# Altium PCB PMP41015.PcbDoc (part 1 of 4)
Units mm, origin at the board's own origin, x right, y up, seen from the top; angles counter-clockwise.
Board outline 173 x 85 mm, 2 copper layers (Top Layer, Bottom Layer), stack 1.575 mm thick; 89 components, 48 nets, 216 pads, 3458 vias.
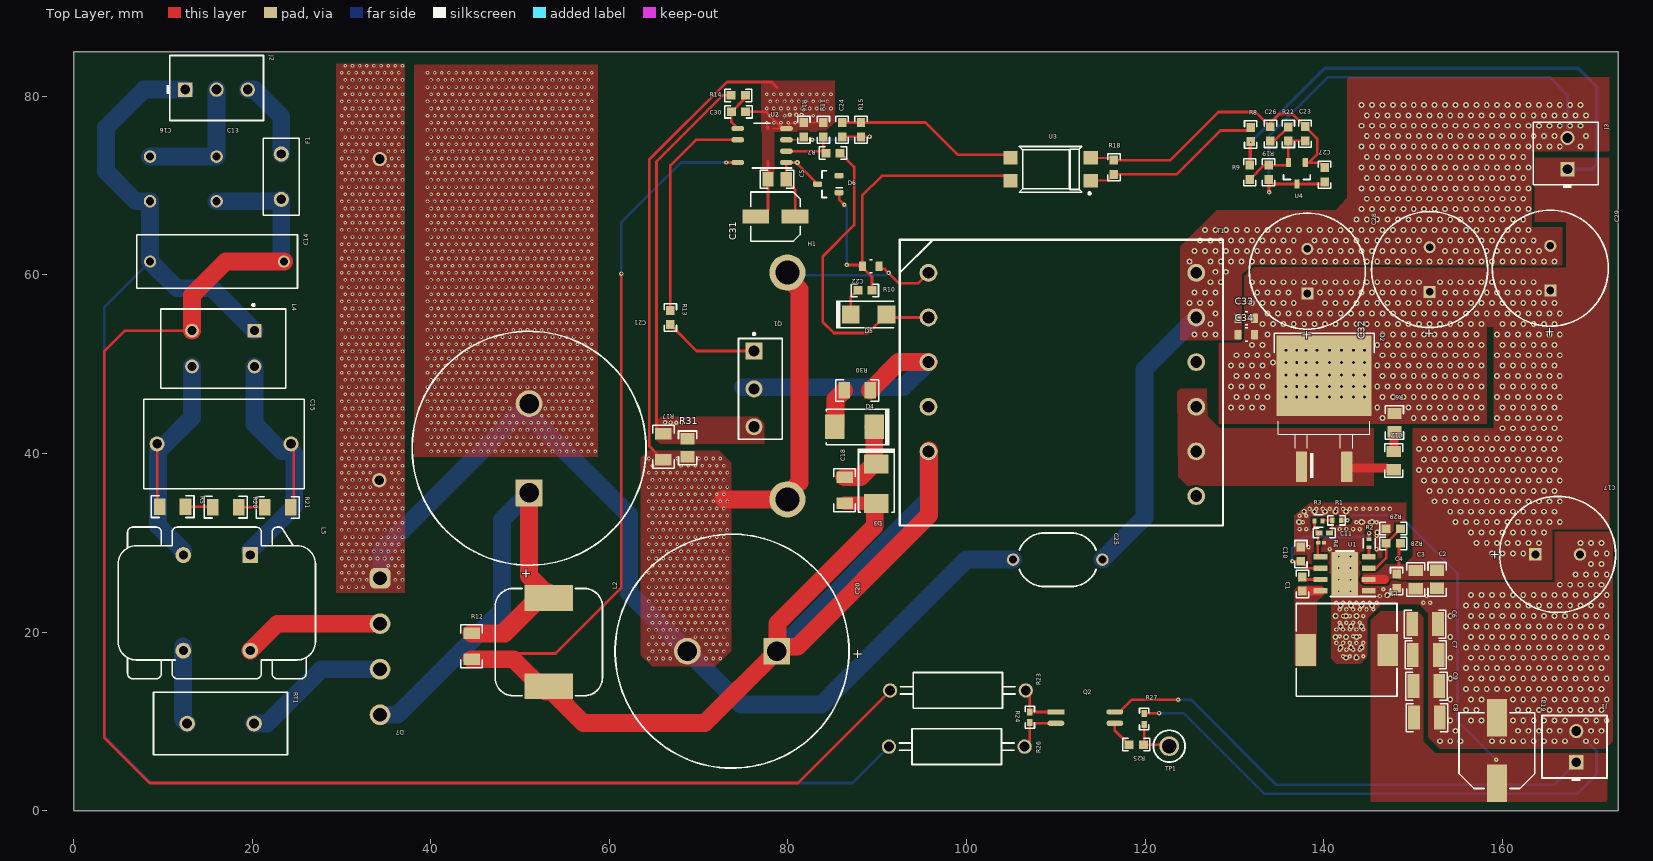
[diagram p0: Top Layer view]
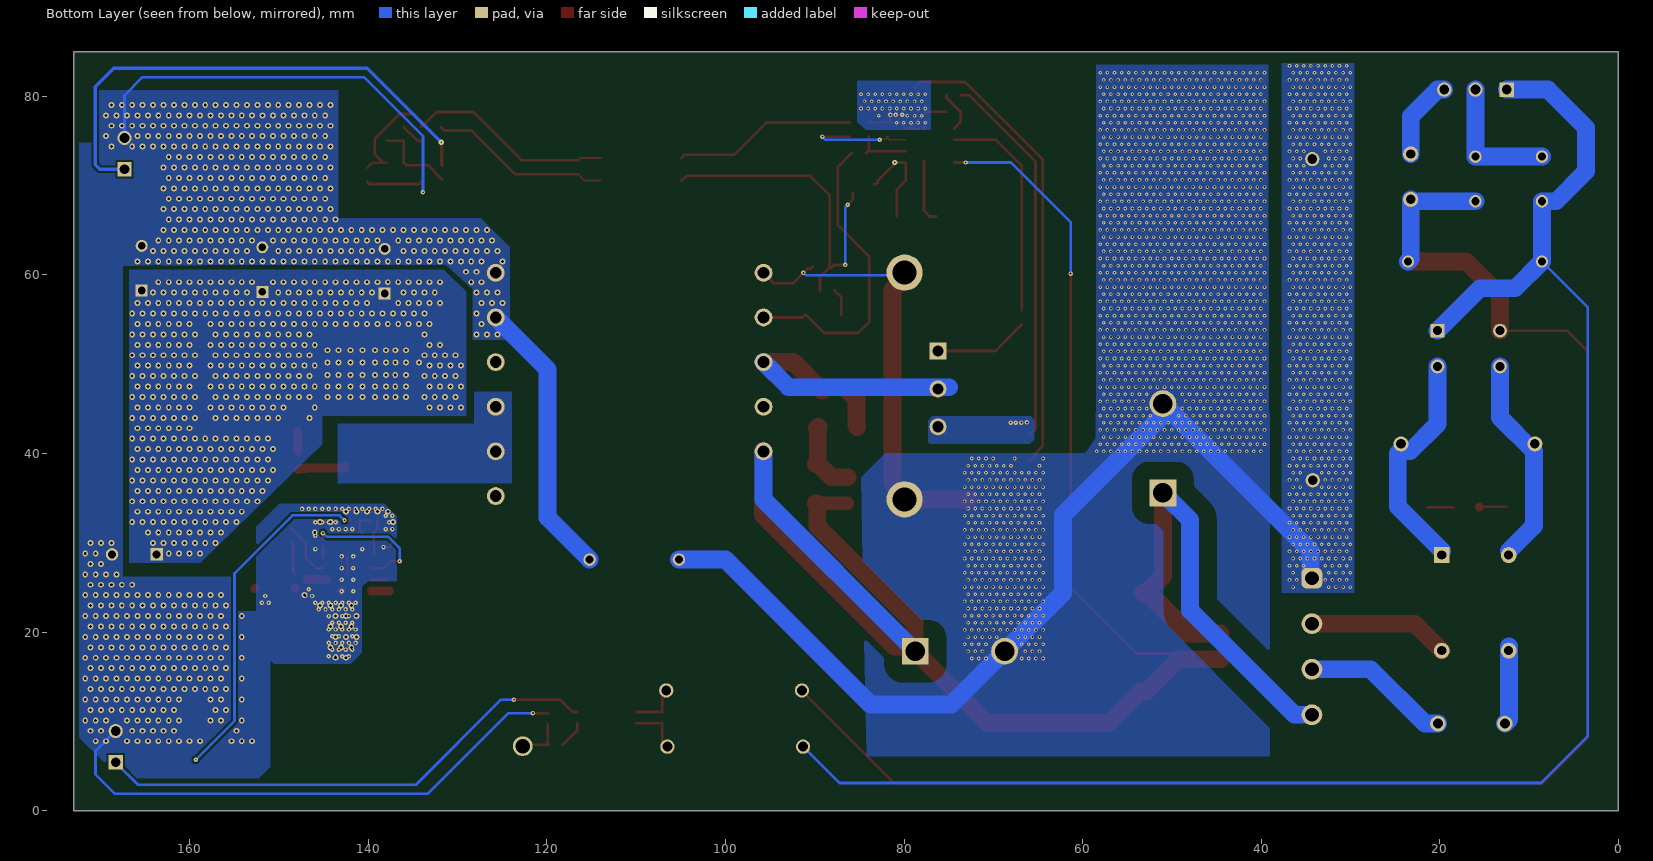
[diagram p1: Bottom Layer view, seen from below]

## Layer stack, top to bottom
Top Solder: solder mask 0.0102, Solder Resist, Dk 3.5
Top Layer: signal copper 0.0356
Dielectric1: core 1.5037, FR-4 High Tg, Dk 4.8
Bottom Layer: signal copper 0.0356
Bottom Solder: solder mask 0.0102, Solder Resist, Dk 3.5

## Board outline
0,0 173,0 173,85 0,85

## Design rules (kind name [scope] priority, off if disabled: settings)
AcuteAngle [All] p1: minimum=4.50000000000000E+0001 checktracksonly=FALSE
AssemblyTestPointUsage [All] p1: valid=2
BoardOutlineClearance BoardOutlineClearance_MountingHoles [OnCopper and InComponentClass('Mounting Holes')] p1: gap=1 ignorepadtopadclearanceinfootprint=FALSE
BoardOutlineClearance BoardOutlineClearance_Poly [OnCopper and IsPoly] p2: gap=0.635 ignorepadtopadclearanceinfootprint=FALSE
BoardOutlineClearance [OnCopper and Not InComponentClass('Logo') and not InComponentClass('FiducialMark') and not InRegion(1000,500,4000,800) and not InPoly] p3: gap=1.016 ignorepadtopadclearanceinfootprint=FALSE
Clearance Clearance_2 [InNet('PGND') vs InNet('NetC21_1')] p1: gap=2 ignorepadtopadclearanceinfootprint=TRUE
Clearance Clearance_1 [InNet('PGND') vs InNet('VDCBUS')] p2: gap=2 ignorepadtopadclearanceinfootprint=TRUE
Clearance Clearance_Keepouts [((IsTrack Or IsArc) And Not InPoly) And IsFree and IsKeepOut vs ((IsTrack Or IsArc) And Not InPoly) And IsFree and IsKeepOut] p3: gap=0 ignorepadtopadclearanceinfootprint=FALSE
Clearance Clearance_Poly [InPolygon] p4: gap=0.254 ignorepadtopadclearanceinfootprint=TRUE
Clearance Clearance_FiducialMark [IsKeepOut and InComponentClass('FiducialMark') vs IsPad and InComponentClass('FiducialMark')] p5: gap=0 ignorepadtopadclearanceinfootprint=FALSE
Clearance [All] p6: gap=0.2 ignorepadtopadclearanceinfootprint=TRUE
ComponentClearance ComponentClearance_MountingHoles_FiducialMarks [InComponentClass('Mounting Holes') vs InComponentClass('FiducialMark')] p1: gap=1.27 collisioncheckmode=3 verticalgap=0.254 showdistances=FALSE
ComponentClearance ComponentClearance_Shunt [InComponentClass('Header') vs InComponentClass('Shunt')] p2: gap=0 collisioncheckmode=3 verticalgap=0 showdistances=FALSE
ComponentClearance ComponentClearance_Logo [InComponentClass('Logo')] p3: gap=0.762 collisioncheckmode=3 verticalgap=0.254 showdistances=FALSE
ComponentClearance ComponentClearance_ScrewToNut [(HasFootprint('NY PMS 440 0025 PH')) vs (HasFootprint('Keystone_1902C'))] p4: gap=0.127 collisioncheckmode=3 verticalgap=0.254 showdistances=FALSE
ComponentClearance ComponentClearance_MountingHoles [InComponentClass('Mounting Holes')] p5: gap=2.54 collisioncheckmode=3 verticalgap=2540 showdistances=FALSE
ComponentClearance ComponentClearance_SmallPassives [HasFootprint('0201*') or HasFootprint('0402*') or HasFootprint('0508') or HasFootprint('0603*') or HasFootprint('0612') or HasFootprint('0805*') or HasFootprint('0815*') or HasFootprint('0830*') or HasFootprint('1206*') or HasFootprint('1210*') or HasFootprint('1808*') or HasFootprint('1812*') or HasFootprint('1825*') or HasFootprint('2010*') or HasFootprint('2220*') or HasFootprint('2225*') or HasFootprint('2512*') or HasFootprint('2728*') or HasFootprint('3518*') vs HasFootprint('0201*') or HasFootprint('0402*') or HasFootprint('0508') or HasFootprint('0603*') or HasFootprint('0612') or HasFootprint('0805*') or HasFootprint('0815*') or HasFootprint('0830*') or HasFootprint('1206*') or HasFootprint('1210*') or HasFootprint('1808*') or HasFootprint('1812*') or HasFootprint('1825*') or HasFootprint('2010*') or HasFootprint('2220*') or HasFootprint('2225*') or HasFootprint('2512*') or HasFootprint('2728*') or HasFootprint('3518*')] p6: gap=0.38 collisioncheckmode=3 verticalgap=0.254 showdistances=FALSE
ComponentClearance ComponentClearance_THtoSMT [IsThruComponent vs IsSMTComponent] p7: gap=0.762 collisioncheckmode=3 verticalgap=0.762 showdistances=FALSE
ComponentClearance ComponentClearance_THtoTH [IsThruComponent vs IsThruComponent] p8: gap=0.508 collisioncheckmode=3 verticalgap=0.762 showdistances=FALSE
ComponentClearance [All] p9: gap=0.508 collisioncheckmode=3 verticalgap=0.254 showdistances=FALSE
DiffPairsRouting [All] p1: maxlimit=2.54 minlimit=0.254 mostfreqgap=0.254 toplayer_minwidth=0.381 toplayer_maxwidth=0.381 toplayer_prefwidth=0.381 bottomlayer_minwidth=0.381 bottomlayer_maxwidth=0.381 bottomlayer_prefwidth=0.381 maxuncoupledlength=25.4
FabricationTestPointUsage TestPointUsage [All] p1: valid=2 allowmultiple=FALSE
FabricationTestpoint Testpoint [All] p1: side=3 testpointundercomponent=TRUE minsize=1.016 maxsize=2.54 preferedsize=1.524 minholesize=0 maxholesize=1.016 preferedholesize=0.813 testpointgrid=0.025 allowsidetop=TRUE allowsidebottom=TRUE usegrid=TRUE gridtolerance=0
FanoutControl Fanout_LCC [IsLCC] p1: bgadir=Out bgaviamode=Centered fanoutstyle=Auto fanoutdirection=Alternating viagrid=0.025 // Fanout_LCC (Default Rule)
FanoutControl Fanout_BGA [IsBGA] p2: bgadir=Out bgaviamode=Centered fanoutstyle=Auto fanoutdirection=Alternating viagrid=0.025 // Fanout_BGA (Default Rule)
FanoutControl Fanout_Default [All] p4: bgadir=Out bgaviamode=Centered fanoutstyle=Auto fanoutdirection=Alternating viagrid=0.025 // Fanout_Default (Default Rule)
FanoutControl Fanout_Small [(CompPinCount < 5)] p5: bgadir=Out bgaviamode=Centered fanoutstyle=Auto fanoutdirection=OutThenIn viagrid=0.025 // Fanout_Small (Default Rule)
HoleSize [All] p1: absolutevalues=TRUE maxlimit=6.375 minlimit=0.2 maxpercent=80.000 minpercent=20.000
MinimumAnnularRing MinimumAnnularRing_ThermalPadVias [IsVia and InAnyComponent] p1: minimumring=0.15
MinimumAnnularRing [All] p2: minimumring=0.2
MinimumSolderMaskSliver MinimumSolderMaskSliver_Logo [InComponentClass('Logo') vs InComponentClass('Logo')] p1: minsoldermaskwidth=0.018
MinimumSolderMaskSliver [All] p2: minsoldermaskwidth=0.1
PlaneConnect [All] p1: planeconnectstyle=Direct reliefexpansion=0.254 reliefentries=4 reliefconductorwidth=0.254 reliefairgap=0.254
PolygonConnect [All] p1: connectstyle=Direct reliefconductorwidth=0.254 reliefentries=4 polygonreliefangle="90 Angle" airgapwidth=0.254
RoutingVias ThermalPadVias [IsVia and InAnyComponent] p1: holewidth=0.2 width=0.5 viastyle="Through Hole" minholewidth=0.1 minwidth=0.1 maxholewidth=0.33 maxwidth=0.6
RoutingVias [All] p2: holewidth=0.406 width=0.864 viastyle="Through Hole" minholewidth=0.1 minwidth=0.1 maxholewidth=1.016 maxwidth=1.651
SilkToBoardRegionClearance [Not ((IsComment or IsDesignator) And (Hide <> 'False')) and not InRegion(1000,500,4000,800)] p1:
SilkToSilkClearance SilkToSilkClearance_Pb-FreeLogo [(HasFootprint('Pb-Free_Overlay_Medium') OR HasFootprint('Pb-Free_Overlay_Small')) vs (HasFootprint('Pb-Free_Overlay_Medium') OR HasFootprint('Pb-Free_Overlay_Small'))] p1: silktosilkclearance=0
SilkToSilkClearance [All] p2: silktosilkclearance=0.1
SilkToSolderMaskClearance SilkToComponentPadClearance [(IsPad or IsFill or IsRegion) and InAnycomponent] p1: minsilkscreentomaskgap=0.127 clearancetoexposedcopper=TRUE
SilkToSolderMaskClearance "Silk to Solder Mask Opening" [All] p2: minsilkscreentomaskgap=0.1 clearancetoexposedcopper=FALSE
SolderMaskExpansion [All] p1: expansion=0.05 istentingtop=FALSE
UnRoutedNet [All] p1: checkbadconnections=TRUE
Width [All] p1: maxlimit=2.54 minlimit=0.3 preferedwidth=2 checkconnectedcopper=TRUE
14 further rules are at their usual default settings.

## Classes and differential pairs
net class "HV BUS": NetQ1_2 VDCBUS
component class PMP41015_DCDC: C1 C2 C3 C4 C6 C7 C8 C9 C10 C11 C17 C19 J1 L1 R1 R2 R3 R4 R28 R29 U1
component class PMP41015_ACDC: C5 C12 C13 C14 C15 C16 C18 C20 C21 C22 C23 C24 C25 C26 C27 C28 C29 C30 C31 C32 C33 C34 D2 D3 D4 D5 D6 D7 F1 H1 J2 J3 L2 L4 L5 Q1 Q2 R5 R6 R7 R8 R9 R10 R11 R12 R13 R14 R15 R16 R17 R18 R19 R20 R21 R22 R23 R24 R25 R26 R27 R30 R31 RT1 T1 TP1 U2 U3 U4

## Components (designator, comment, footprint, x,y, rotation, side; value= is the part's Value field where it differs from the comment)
C1 "0.1uF" 0603 137.623,25.377 r270 top
C2 "4.7uF" 0805_HV 152.704,25.908 r270 top
C3 "4.7uF" 0805_HV 150.316,25.883 r270 top
C4 "0.22uF" 0603 148.178,25.705 r270 top
C5 "C2012X7R1H225K125AC" 0805_HV 78.774,70.726 r180 top value=2.2uF
C6 "" 1210 151.359,20.879 r0 top value=22uF
C7 "CMP-0009169-2" 1210 151.435,17.45 r0 top value=22uF
C8 "CMP-0009169-2" 1210 151.565,10.414 r0 top value=22uF
C9 "CMP-0009169-2" 1210 151.511,13.945 r0 top value=22uF
C10 "CMP-0006833-4" 0603 137.446,28.73 r90 top value=1uF
C11 "CMP-0006207-2" 0402 140.073,31.09 r180 top value=10pF
C12 "CMP-0007712-2" 0805_HV 147.852,39.208 r90 top value=1000pF
C13 "VY2222M35Y5UG6TV5" VY2_900x500_5 16,70.75 r90 top value=2200pF
C14 "ECQ-U2A104ML" CAPRR1500W60L1750T550H1250 16.05,61.5 r180 top value=0.1uF
C15 "ECQ-U2A334ML" CAPRR1500W80L1750T950H1750 16.84,41.072 r0 top value=0.33uF
C16 "VY2222M35Y5UG6TV5" VY2_900x500_5 8.55,70.75 r270 top value=2200pF
C17 "CMP-0010315-2" B41896_1250x2500 166.206,28.695 r0 top value=680uF
C18 "CMP-0008891-2" 1206 86.335,35.89 r90 top value=1000pF
C19 "CMP-0010819-1" CAPSMT_62_HA0 159.41,6.731 r90 top value=680uF
C20 "CMP-0010099-2" Nichicon_2500x3000_Snap 73.736,17.856 r180 top value=120uF
C21 "CMP-0010099-2" Nichicon_2500x3000_Snap 51.003,40.585 r90 top value=120uF
C22 "CGA4J1X7R1H475K125AC" FP-CGA4J1X7R1H475K125AC_0805-MFG 89.29,60.96 r180 top value=4.7µF
C23 "06035C561KAT2A" 0603 137.922,75.815 r90 top value=560pF
C24 "CMP-0007015-5" 0603 86.064,76.27 r90 top value=0.047uF
C25 "CD45-E2GA222M-NKA" CD45_900x600x1300 110.211,28.118 r0 top value=2200pF
C26 "C0603C332F5GACTU" 0603 134.036,75.791 r90 top value=3300pF
C27 "CMP-0006752-5" 0603 140.106,71.209 r270 top value=0.1uF
C28 "ELXZ350ELL102MK25S" Chemi-Con_1250x2000 138.168,60.42 r90 top value=1000uF
C29 "ELXZ350ELL102MK25S" Chemi-Con_1250x2000 165.384,60.754 r90 top value=1000uF
C30 "CMP-0006939-4" 0603 74.464,78.27 r0 top value=47pF
C31 "CMP-0011424-2" SM_RADIAL_5MM 78.603,66.541 r180 top value=4.7uF
C32 "ELXZ350ELL102MK25S" Chemi-Con_1250x2000 151.869,60.599 r90 top value=1000uF
C33 "C2012X7R1H475K125AC" FP-C2012X7R1H475K125AC_0805-MFG 131.343,55.143 r0 top
C34 "C2012X7R1H475K125AC" FP-C2012X7R1H475K125AC_0805-MFG 131.343,53.315 r0 top
D2 "MBRB20200CTT4G" DDPAK 140.046,44.743 r90 top value=200V
D3 "CMP-0005579-3" SMB 89.891,36.601 r270 top value=170V
D4 "CMP-0076889-2" SMB 87.452,42.977 r180 top value=1000V
D5 "US1J-13-F" SMA 89.027,55.575 r0 top value=600V
D6 "CMP-0028436-2" SOT-23 84.518,70.162 r180 top value=40V
D7 "KBU8J-E4/51" KBU 32.795,18.383 r270 top value=600V
F1 "39215000000" FUSE_392 23.25,71 r90 top
H1 "V6560W" HSINK_V6560W 79.93,47.562 r270 top
J1 "0393570002" MOLEX_39357-0002 168.3,7.163 r90 top
J2 "0393570003" MOLEX_39357-0003 16,80.75 r0 top
J3 "0393570002" MOLEX_39357-0002 167.307,73.594 r90 top
L1 "=Value" WE-HCC_1090 142.573,18.009 r0 top
L2 "7447709821" WE-PD_1210 53.211,18.876 r270 top value=820uH
L4 "750343092" FP-750343092_PTH_14MM0_8MM89-0 16.75,51.75 r270 top
L5 "744823220" WE-CMB_M 16.027,23.266 r270 top value=20mH
Q1 "TK10A80W" FP-IPAW60R360P7SXKSA1_PG-TO220-3-MFG 76.898,47.236 r0 top
Q2 "TLP292(GR-TPL,E" FP-TLP292(GR-TPL,E_SO4-IPC_A 113.303,10.418 r0 top
R1 "CMP-0026765-1" CPF0402 141.453,32.512 r0 top value=10.0
R2 "CRCW0402100KFKEDC" FP-CRCW0402100KFKEDC_0402-MFG 145.085,29.947 r90 top value=100k
R3 "CRCW0402100KFKEDC" FP-CRCW0402100KFKEDC_0402-MFG 139.421,32.436 r0 top value=100k
R4 "RC0201FR-0723K7L" 0201 139.724,29.987 r180 top value=23.7k
R5 "CMP-0017156-3" 1206 11.074,34.036 r180 top value=750k
R6 "CMP-0020804-2" 0805_HV 147.926,43.456 r90 top value=10
R7 "CMP-0022628-4" 0603 85.039,73.64 r0 top value=86.6k
R8 "CMP-0022883-5" 0603 131.826,75.726 r270 top value=1.50k
R9 "CMP-0024170-3" 0603 131.724,71.488 r90 top value=383k
R10 "CMP-0025703-4" 0603 88.621,58.268 r180 top value=10
R11 "CMP-0022220-4" 0603 83.964,76.27 r270 top value=22.1k
R12 "CMP-0018656-3" 1206 44.571,18.397 r270 top value=330k
R13 "ERJ-3RQF2R2V" 0603 66.827,55.234 r270 top value=2.20
R14 "CMP-0022109-5" 0603 74.435,80.11 r180 top value=1.00k
R15 "CMP-0022735-5" 0603 88.181,76.27 r270 top value=100k
R16 "CMP-0022925-5" 0603 81.775,76.249 r270 top value=22.0k
R17 "CMP-0017788-3" 1206 66.048,40.767 r90 top value=0.33
R18 "CMP-0023354-3" 0603 116.51,72.06 r270 top value=4.99k
R19 "CMP-0023118-5" 0603 133.833,71.488 r90 top value=44.2k
R20 "CMP-0017156-3" 1206 17.018,33.985 r180 top value=750k
R21 "CMP-0017156-3" 1206 22.86,33.96 r180 top value=750k
R22 "CMP-0021998-4" 0603 136.043,75.79 r270 top value=10.0k
R23 "CMP-0014401-2" PR02 99.035,13.462 r0 top value=47k
R24 "CMP-0026891-5" 0402 107.088,10.453 r90 top value=2.4k
R25 "CMP-0025697-4" 0603 118.999,7.391 r0 top value=0
R26 "CMP-0014401-2" PR02 98.908,7.163 r0 top value=47k
R27 "CMP-0025983-3" 0402 119.893,10.262 r270 top value=120k
R28 "CMP-0021990-4" 0603 147.797,29.919 r0 top value=100k
R29 "CMP-0022746-5" 0603 147.803,31.595 r0 top value=10.0k
R30 "CMP-0018687-3" 1206 87.757,47.066 r180 top value=47
R31 "CMP-0020847-3" 0805_HV 68.759,40.634 r90 top value=10.0
RT1 "B57237S0479M000" S237 16.452,9.75 r0 top value=4.7
T1 "750345036" "EE28 FROM CUSTOMER" 95.733,60.234 r0 top value=300uH
TP1 "5011" Keystone5011 122.707,7.216 r180 top
U1 "LMR33620ADDAR" DDA0008J 142.348,26.518 r180 top
U2 "UCC28740DR" D0007A_N 77.1,74.495 r180 top
U3 "LTV-817S" DIP254P762X350-4 109.423,71.831 r180 top
U4 "TL431LIBQDBZR" DBZ0003A_N 137.008,71.378 r270 top

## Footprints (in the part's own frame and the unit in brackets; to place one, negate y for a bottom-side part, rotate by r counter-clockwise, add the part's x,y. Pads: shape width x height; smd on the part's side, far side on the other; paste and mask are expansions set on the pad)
0201 [mm] "Data from Kemet datasheet CC101_COM dated 7/28/11"
  rect 0.46x0.42 smd mask+0.048: 1(-0.33,0) 2(0.33,0)
  body extent -0.31,-0.16 0.31,0.16, height 0.26
0402 [mm] "0402 from SM-752 data"
  rect 0.8x0.6 smd: 1(-0.6,0) 2(0.6,0)
  silkscreen extent -1.22,-0.52 1.22,0.52, body extent -0.55,-0.3 0.55,0.3, height 0.6
0603 [mm] "0603 from SM-752 data"
  rect 1x0.95 smd: 1(-0.8,0) 2(0.8,0)
  silkscreen extent -1.52,-0.69 1.52,0.69, body extent -0.87,-0.47 0.87,0.47, height 1
0805_HV [mil] "0805 with 30mil clearance between pads"
  rect 50x63 smd: 1(-40,0) 2(40,0)
  silkscreen extent -74,-40 74,40, body extent -43,-29 43,29, height 57
1206 [mm] "1206 from SM-752 data"
  rect 1.3x1.85 smd: 1(-1.45,0) 2(1.45,0)
  silkscreen extent -2.4,-1.21 2.4,1.21, body extent -1.7,-0.9 1.7,0.9, height 1.35
1210 [mm] "1210 from SM-752 data"
  rect 1.3x2.7 smd: 1(-1.45,0) 2(1.45,0)
  silkscreen extent -2.32,-1.57 2.32,1.57, body extent -1.7,-1.35 1.7,1.35, height 1.35
B41896_1250x2500 [mm] "TH, 2-Leads, Dia 12.5mm, Pin Spacing 5mm"
  rect 1.4x1.4 hole 0.9: 1(-2.5,0)
  round 1.4 hole 0.9: 2(2.5,0)
  silkscreen extent -6.5,-6.5 6.5,6.5, body extent -6.5,-6.5 6.51,6.5, height 27.01
CAPRR1500W60L1750T550H1250 [mm] "PANASONIC"
  round 1.35 hole 0.85: 1(-7.5,0) 2(7.5,0)
  silkscreen extent -9,-3 9,3, body extent -9.05,-3.05 9.05,3.05, height 13
CAPRR1500W80L1750T950H1750 [mm] "PANASONIC"
  round 1.7 hole 1.069: 1(-7.5,0) 2(7.5,0)
  silkscreen extent -9,-5 9,5, body extent -9,-5 9,5, height 18
CAPSMT_62_HA0 [mm] "8 x 10mm:  Chemi-Con HA0"
  rect 4.2x2.2 smd: 1(-3.65,0) 2(3.65,0)
  silkscreen extent -4.25,-4.25 4.25,4.25, body extent -4.25,-4.25 4.25,4.25, height 10.5
CD45_900x600x1300 [mm] "TH, 2-Leads, Dia 9mm, Pin Spacing 10 mm"
  round 1.4 hole 0.9: 1(-5,0) 2(5,0)
  silkscreen extent -4.29,-3.02 4.3,2.98, body extent -5.39,-3.01 5.39,3.01, height 13
Chemi-Con_1250x2000 [mm] "TH, 2-Leads, Dia 12.5mm, Lead Sapcing 5mm"
  rect 1.35x1.35 hole 0.85: 1(-2.5,0)
  round 1.35 hole 0.85: 2(2.5,0)
  silkscreen extent -6.5,-6.5 6.5,6.5, body extent -6.5,-6.5 6.51,6.5, height 21.5
CPF0402 [mm] "TE Connectivity"
  rect 0.5x0.6 smd: 1(-0.5,0) 2(0.5,0)
  silkscreen extent -0.97,-0.53 0.97,0.53, body extent -0.55,-0.27 0.55,0.27, height 0.35
D0007A_N [mm] "SOIC, 7-Leads, Body 4.9x3.9mm, Pitch 1.27mm, IPC Medium Density"
  oval 1.45x0.6 smd: 1(-2.725,1.905) 2(-2.725,0.635) 3(-2.725,-0.635) 4(-2.725,-1.905) 5(2.725,-1.905) 6(2.725,-0.635) 8(2.725,1.905)
  silkscreen extent -3.32,-2.5 1.1,2.52, body extent -3.01,-2.45 3.01,2.45, height 1.75
DBZ0003A_N [mm] "SOT23, 3-Leads, Body 2.9x1.3mm, Pitch 0.95mm, Lead Span 2.4mm, IPC Medium Density"
  rrect17% 1x0.6 smd: 1(-1.2,0.95) 2(-1.2,-0.95) 3(1.2,0)
  silkscreen extent 0.2,-1.5 0.7,1.5, body extent -1.26,-1.46 1.26,1.46, height 0.98
DDA0008J [mm] "SOIC, 8-Leads, Body 4.9x3.9mm, Pitch 1.27mm, Exposed Pad"
  rrect14% 1.55x0.6 smd: 1(-2.7,1.905) 2(-2.7,0.635) 3(-2.7,-0.635) 4(-2.7,-1.905) 5(2.7,-1.905) 6(2.7,-0.635) 7(2.7,0.635) 8(2.7,1.905)
  rrect4% 2.95x4.9 smd paste-1.5 mask-1.5: 9(0,0)
  silkscreen extent -3.47,-2.55 1.58,2.55, body extent -3.01,-2.45 3.01,2.45, height 1.57
DDPAK [mil] "D2-PAK, 3-Pads, Body 9.7x10.4mm (max), TO-263AB, using Vishay Silionix recommended pad sizes"
  rrect8% 135x49.49 smd: 1(-246.06,100) 3(-246.06,-100)
  rrect1% 355x420 smd paste-181.1: 4(155.51,0)
  silkscreen extent -295,-220 344,220, body extent -295,-202 324,202, height 180
DIP254P762X350-4 [mm] "LITE-ON"
  rect 1.6x1.5 smd: 1(-4.5,1.27) 2(-4.5,-1.27) 3(4.5,-1.27) 4(4.5,1.27)
  silkscreen extent -4.47,-2.55 3.5,2.82, body extent -5.23,-2.55 5.23,2.55, height 4.62
"EE28 FROM CUSTOMER" [mm]
  round 2 hole 1.32: 1(0,0) 2(0,-5) 3(0,-10) 4(0,-15) 5(0,-20) 7(30,-25) 8(30,-20) 9(30,-15) 10(30,-10) 11(30,-5) 12(30,0)
  round 0 all layers, no hole: 6(0,-25)
  silkscreen extent -3.2,-28.3 33,3.7
FP-750343092_PTH_14MM0_8MM89-0 [mm]
  rrect6% 1.55x1.55 hole 1 paste-1000 mask+0: 1(-2,3.5)
  round 1.55 hole 1 paste-1000 mask+0: 2(2,3.5) 3(2,-3.5) 4(-2,-3.5)
  silkscreen extent -5,-7 4.45,7, body extent -4.61,-7 4.58,7, height 18.5
FP-C2012X7R1H475K125AC_0805-MFG [mm]
  rrect13% 0.8x1.05 smd paste+0 mask+0: 1(-0.925,0) 2(0.925,0)
  silkscreen extent -0.15,-0.75 0.15,0.75, body extent -1.43,-0.85 1.43,0.85, height 0.25
FP-CGA4J1X7R1H475K125AC_0805-MFG [mm]
  rrect13% 0.8x1.05 smd paste+0 mask+0: 1(-0.925,0) 2(0.925,0)
  silkscreen extent -0.15,-0.72 0.15,0.72, body extent -1.43,-0.82 1.43,0.82, height 0.25
FP-CRCW0402100KFKEDC_0402-MFG [mm]
  rrect25% 0.4x0.6 smd paste+0 mask+0: 1(-0.45,0) 2(0.45,0)
  silkscreen extent -0.55,-0.67 0.55,0.67, body extent -0.5,-0.25 0.5,0.25, height 0.35
FP-IPAW60R360P7SXKSA1_PG-TO220-3-MFG [mm]
  rrect5% 1.9x1.9 hole 1.25 paste-1000 mask+0: 1(-0.7,4.25)
  round 1.9 hole 1.25 paste-1000 mask+0: 2(-0.7,0) 3(-0.7,-4.25)
  silkscreen extent -2.45,-5.65 2.45,6.27, body extent -2.55,-5.75 2.55,5.75, height 0.25
FP-TLP292(GR-TPL,E_SO4-IPC_A [mm]
  rect 1.903x0.592 smd paste+0 mask+0: 1(-3.3,0.635)
  oval 1.903x0.592 smd paste+0 mask+0: 2(-3.3,-0.635) 3(3.3,-0.635) 4(3.3,0.635)
  body extent -3.5,-1.3 3.5,1.3, height 2.31
FUSE_392 [mm] "LITTELFUSE"
  round 1.7 hole 1.05: 1(-2.54,0) 2(2.54,0)
  silkscreen extent -4.32,-2.03 4.32,2.03, body extent -4.25,-2 4.25,2, height 8
HSINK_V6560W [mm] "Heat Sink TO-220"
  round 4.05 hole 2.7: 1(-12.7,0) 2(12.7,0)
  body extent -15,-9 15,3, height 25
KBU [mm] "TH, 4-Leads, Body 23.2x6.85mm, Pitch 5.1mm"
  rrect50% 2.325x2.325 hole 1.55: 1(-7.65,1.525)
  round 2.325 hole 1.55: 2(-2.55,1.525) 3(2.55,1.525) 4(7.65,1.525)
  body extent -11.6,-3.43 11.6,3.52, height 18.7
Keystone5011 [mil] "Keystone Multipurpose loops"
  round 87 hole 63: 1(0,0)
  silkscreen extent -70,-70 70,70, body extent -63,-63 63,62, height 319
MOLEX_39357-0002 [mm] "Terminal Block, 3.5 mm, 2x1, TH"
  rect 1.6x1.6 hole 1.1: 1(-1.75,0)
  round 1.6 hole 1.1: 2(1.75,0)
  silkscreen extent -3.86,-3.45 3.5,3.84, body extent -3.55,-3.45 3.56,3.84, height 8.51
MOLEX_39357-0003 [mm] "Terminal Block, 3.5 mm, 3x1, TH"
  rect 1.6x1.6 hole 1.1: 1(-3.5,0)
  round 1.6 hole 1.1: 2(0,0) 3(3.5,0)
  silkscreen extent -5.61,-3.45 5.25,3.84, body extent -5.25,-3.45 5.16,3.84, height 8.51
Nichicon_2500x3000_Snap [mm]
  rrect3% 3x3 hole 2.2: 1(-5,0)
  round 3 hole 2.2: 2(5,0)
  silkscreen extent -13.1,-13.1 13.1,13.1, body extent -13,-13 13.01,13, height 32.01
PR02 [mm] "Vishay-BC Components"
  round 1.6 hole 1.1: 1(-7.6,0) 2(7.6,0)
  silkscreen extent -6.42,-2 6.42,2, body extent -8.02,-2 8.02,2, height 3.98
S237 [mm] "EPCOS"
  round 1.75 hole 1.1: 1(-3.75,0) 2(3.75,0)
  silkscreen extent -7.5,-3.5 7.5,3.5, body extent -7.47,-3.5 7.47,3.5, height 21.99
SM_RADIAL_5MM [mm] "Nichicon 5x5.8"
  rect 3x1.6 smd: 1(-2.2,0) 2(2.2,0)
  silkscreen extent -2.75,-2.75 2.75,2.75, body extent -2.75,-2.75 2.75,2.75, height 6.1
SMA [mm] "Molded Diode, 2-Leads, Body 4.3x2.6mm, IPC Medium Density, based on OnSemi component dimensions and land pattern"
  rect 2x2 smd: 1(-2,0) 2(2,0)
  silkscreen extent -3.66,-1.57 2.79,1.57, body extent -2.6,-1.3 2.6,1.3, height 2.42
SMB [mm] "Molded Diode, 2-Leads, Body 5.4x3.6mm, IPC Medium Density, based on OnSemi component dimensions"
  rect 2.159x2.743 smd: 1(-2.21,0) 2(2.21,0)
  silkscreen extent -3.94,-2.08 3.18,2.08, body extent -2.7,-1.8 2.7,1.8, height 2.32
SOT-23 [mm] "SOT23, 3-Leads, Body 2.9x1.3mm, Pitch 0.95mm, Lead Span 2.5mm, IPC Medium Density"
  rrect50% 1x0.6 smd: 1(-1.2,0.95) 2(-1.2,-0.95) 3(1.2,0)
  silkscreen extent -1.62,-1.5 0.7,1.5, body extent -1.16,-1.45 1.21,1.45, height 1
VY2_900x500_5 [mm] "TH, 2-Leads, Body 9x5mm, Lead Spacing 5mm"
  round 1.4 hole 0.9: 1(-2.5,0) 2(2.5,0)
  body extent -4.5,-2.5 4.5,2.5, height 13
WE-CMB_M [mil] "Wurth"
  rect 70x70 hole 40: 1(-210.63,147.64)
  round 70 hole 40: 2(-210.63,-147.64) 3(210.63,-147.64) 4(210.63,147.64)
  silkscreen extent -335,-435 335,435, body extent -335,-394 335,394, height 1044
WE-HCC_1090 [mm] "SMT High Current Cube Inductor, 2-Leads, body 10.9x10mm"
  rect 2.3x3.6 smd: 1(-4.6,0) 2(4.6,0)
  silkscreen extent -5.65,-5.2 5.65,5.2, body extent -5.12,-5 5.13,5, height 9.3
WE-PD_1210 [mm] "Wurth Elektronik recommended land pattern"
  rect 2.9x5.4 smd: 1(-4.95,0) 2(4.95,0)
  silkscreen extent -6,-6 6,6, body extent -6,-6 6,6, height 10.01

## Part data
C1: library part CMP-0006753-4, "CAP, CERM, 0.1 uF, 25 V, +/- 10%, X7R, 0603", Cap_Case=0603, Manufacturer=AVX, PartNumber=06033C104KAT2A, Supplier Part Number 1=478-3714-1-ND, TempCo=X7R, Tolerance_%=10%, Value1="0.05 ohm", Value2=25V
C2 C3: library part CMP-0007840-2, "CAP, CERM, 4.7 uF, 50 V, +/- 10%, X5R, 0805", Cap_Case=0805, Manufacturer=TDK, PartNumber=C2012X5R1H475K125AB, Supplier Part Number 1=445-5980-1-ND, TempCo=X5R, Tolerance_%=10%, Value1="0.002346 ohm", Value2=50V
C4: library part CMP-0007047-4, "CAP, CERM, 0.22 uF, 50 V, +/- 10%, X7R, 0603", Cap_Case=0603, Manufacturer=TDK, PartNumber=C1608X7R1H224K080AB, Supplier Part Number 1=445-7408-1-ND, TempCo=X7R, Tolerance_%=10%, Value1="0.021699 ohm", Value2=50V
C5: library part CMP-0007877-2, "CAP, CERM, 2.2 uF, 50 V, +/- 10%, X7R, 0805", Cap_Case=0805, Manufacturer=TDK, Supplier Part Number 1=445-5968-1-ND, TempCo=X7R, Tolerance_%=10%, Value1="0.00366 ohm", Value2=50V, ValueDisplayed=2.2uF
C6: library part CMP-0009169-2, "CAP, CERM, 22 uF, 25 V, +/- 10%, X5R, 1210", Cap_Case=1210, Manufacturer="Samsung Electro-Mechanics", PartNumber=CL32A226KAJNNNE, TempCo=X5R, Tolerance_%=10%, Value1=Unknown, Value2=25V, ValueDisplayed=22uF
C7 C8 C9: "CAP, CERM, 22 uF, 25 V, +/- 10%, X5R, 1210", Cap_Case=1210, Manufacturer="Samsung Electro-Mechanics", PartNumber=CL32A226KAJNNNE, TempCo=X5R, Tolerance_%=10%, Value1=Unknown, Value2=25V, ValueDisplayed=22uF
C10: "CAP, CERM, 1 uF, 25 V, +/- 10%, X7R, 0603", Cap_Case=0603, Manufacturer="Wurth Elektronik", PartNumber=885012206076, Supplier Part Number 1=732-7994-1-ND, TempCo=X7R, Tolerance_%=10%, Value1=Unknown, Value2=25V, ValueDisplayed=1uF
C11: "CAP, CERM, 10 pF, 50 V, +/- 5%, C0G/NP0, 0402", Cap_Case=0402, Manufacturer="Johanson Technology", PartNumber=500R07S100JV4T, TempCo=C0G/NP0, Tolerance_%=5%, Value1=Unknown, Value2=50V, ValueDisplayed=10pF
C12: "CAP, CERM, 1000 pF, 630 V, +/- 5%, X7R, 0805", Cap_Case=0805, Manufacturer=Kemet, PartNumber=C0805C102JBRACTU, Supplier Part Number 1=399-5574-1-ND, TempCo=X7R, Tolerance_%=5%, Value1=Unknown, Value2=630V, ValueDisplayed=1000pF
C13 C16: library part CMP-0080613-1, "CAP, CERM, 2200 pF, X1 440 VAC/Y2 300 VAC, +/- 20%, Y5U, Body9x5mm", Cap_Case=9x5mm, Manufacturer=Vishay-Bccomponents, TempCo=Y5U, Tolerance_%=20%, ValueDisplayed=2200pF
C14: library part CMP-0012496-1, "CAP, Film, 0.1 uF, 275 V, +/- 20%, TH", Cap_Case="Radial 17.5x5.5x12.5", Manufacturer=Panasonic, Supplier Part Number 1=P10730-ND, Tolerance_%=20%, Value1=Unknown, Value2=275V, ValueDisplayed=0.1uF
C15: library part CMP-0012499-3, "CAP, Film, 0.33 uF, 275 V, +/- 20%, TH", Cap_Case=Radial,17.5x17.5x9.5mm, Manufacturer=Panasonic, Supplier Part Number 1=P10733-ND, Tolerance_%=20%, Value1=Unknown, Value2=275V, ValueDisplayed=0.33uF
C17: "CAP, AL, 680 uF, 35 V, +/- 20%, 0.041 ohm, AEC-Q200 Grade 1, TH", Cap_Case=12.5x25mm, Manufacturer=TDK, PartNumber=B41896C7687M000, Supplier Part Number 1=495-6062-ND, Tolerance_%=20%, Value1="0.041 ohm", Value2=35V, ValueDisplayed=680uF
C18: "CAP, CERM, 1000 pF, 630 V, +/- 5%, U2J, 1206", Cap_Case=1206, Manufacturer=MuRata, PartNumber=GRM31A7U2J102JW31D, Supplier Part Number 1=490-4296-1-ND, TempCo=U2J, Tolerance_%=5%, Value1=Unknown, Value2=630V, ValueDisplayed=1000pF
C19: "CAP, AL, 680 uF, 6.3 V, +/- 20%, SMD", Cap_Case=HA0, Manufacturer=Chemi-Con, PartNumber=EMVA6R3ADA681MHA0G, Supplier Part Number 1=565-2061-1-ND, Tolerance_%=20%, Value1=Unknown, Value2=6.3V, ValueDisplayed=680uF
C20 C21: "CAP, AL, 120 uF, 450 V, +/- 20%, TH", Cap_Case=25x30mm, Manufacturer=Nichicon, PartNumber=LLS2W121MELA, Supplier Part Number 1=493-2602-ND, Tolerance_%=20%, Value1=Unknown, Value2=450V, ValueDisplayed=120uF
C22: library part CMP-0090082-1, "Cap Ceramic 4.7uF 50V X7R 10% Pad SMD 0805 +125°C Automotive T/R", Manufacturer="TDK Corporation", Operating Temperature Range="-55°C to +125°C", TempCo=15%, Temperature Characteristic=X7R, Tolerance_%=0.1%, ValueDisplayed=4.7uF
C23: library part CMP-0006807-4, "CAP, CERM, 560 pF, 50 V, +/- 10%, X7R, 0603", Cap_Case=0603, Manufacturer=AVX, Supplier Part Number 1=478-1212-1-ND, TempCo=X7R, Tolerance_%=10%, Value1=Unknown, Value2=50V, ValueDisplayed=560pF
C24: "CAP, CERM, 0.047 uF, 50 V, +/- 10%, X5R, 0603", Cap_Case=0603, Manufacturer=TDK, PartNumber=C1608X5R1H473K080AA, Supplier Part Number 1=445-14155-1-ND, TempCo=X5R, Tolerance_%=10%, Value1="0.049007 ohm", Value2=50V, ValueDisplayed=0.047uF
C25: library part CMP-0009597-2, "CAP, CERM, 2200 pF,  V, +/- 20%, E, D9xT6mm", Cap_Case=9x6x13mm, Manufacturer=TDK, Supplier Part Number 1=445-174537-ND, TempCo=E, Tolerance_%=20%, Value1=Unknown, Value2=V, ValueDisplayed=2200pF
C26: library part CMP-0081060-1, "CAP, CERM, 3300 pF, 50 V,+/- 1%, C0G/NP0, 0603", Cap_Case=0603, Manufacturer=Kemet, Supplier Part Number 1=399-11151-1-ND, TempCo=C0G/NP0, Tolerance_%=1%, Value2=50V, ValueDisplayed=3300pF
C27: "CAP, CERM, 0.1 uF, 25 V, +/- 5%, X7R, 0603", Cap_Case=0603, Manufacturer=AVX, PartNumber=06033C104JAT2A, Supplier Part Number 1=478-3713-1-ND, TempCo=X7R, Tolerance_%=5%, Value1="0.05 ohm", Value2=25V, ValueDisplayed=0.1uF
C28 C29 C32: library part CMP-0010484-2, "CAP, AL, 1000 uF, 35 V, +/- 20%, AEC-Q200 Grade 2, TH", Cap_Case=12.5x25mm, Manufacturer=Chemi-Con, Supplier Part Number 1=565-1989-ND, Tolerance_%=20%, Value1=Unknown, Value2=35V, ValueDisplayed=1000uF
C30: "CAP, CERM, 47 pF, 50 V, +/- 5%, C0G/NP0, 0603", Cap_Case=0603, Manufacturer=Kemet, PartNumber=C0603C470J5GACTU, Supplier Part Number 1=399-1056-1-ND, TempCo=C0G/NP0, Tolerance_%=5%, Value1=Unknown, Value2=50V, ValueDisplayed=47pF
C31: "CAP, AL, 4.7 uF, 50 V, +/- 20%, 1.52 ohm, SMD", Cap_Case=5x5.8, Manufacturer=Nichicon, PartNumber=UUD1H4R7MCL1GS, Supplier Part Number 1=493-2297-1-ND, Tolerance_%=20%, Value1="1.52 ohm", Value2=50V, ValueDisplayed=4.7uF
C33 C34: library part CMP-0088943-1, "4.7µF ±10% 50V Ceramic Capacitor X7R 0805 (2012 Metric)", Digikey Part Number=445-C2012X7R1H475K125ACCT-ND, Manufacturer=TDK, Mouser Part Number=810-C2012X7R475K125C, Operating Temperature Range="-55°C to +125°C", TempCo=15%, Temperature Characteristic=X7R, Tolerance_%=10%, ValueDisplayed=4.7uF
D2: library part CMP-0028500-1, "Diode, Schottky, 200 V, 20 A, DDPAK", Manufacturer="ON Semiconductor", Supplier Part Number 1=MBRB20200CTT4GOSCT-ND, Value1=20A, Value2=1V
D3: "Diode, TVS, Uni, 170 V, 275 Vc, SMB", Manufacturer="Diodes Inc.", PartNumber=SMBJ170A-13-F, Value1=600W
D4: "Diode, P-N, 1000 V, 1 A, SMB", Manufacturer="Diodes Inc.", PartNumber=RS1MB-13-F, Value1=1A, Value2=1.3V
D5: library part CMP-0077027-2, "Diode, Ultrafast, 600 V, 1 A, SMA", Manufacturer="Diodes Inc.", Value1=1A, Value2=1.7V
D6: "Diode, Schottky, 40 V, 0.2 A, SOT-23", Manufacturer="Diodes Inc.", PartNumber=BAS40-7-F, Value1=0.2A, Value2=0.8V
D7: library part CMP-0085999-1, "Diode, Switching-Bridge, 600 V, 8 A, TH", Manufacturer=Vishay-Semiconductor, Value1=8A, Value2=1V
F1: library part CMP-0003562-2, "Fuse, 5 A, 250VAC/VDC, TH", Irating_A=5A, Manufacturer=Littelfuse, Supplier Part Number 1=39215000000-ND
H1: library part CMP-0086362-1, "Heat Sink TO-220", Manufacturer="Assman WSW"
J1 J3: library part CMP-0055341-2, "Terminal Block, 3.5 mm, 2x1, Tin, TH", Manufacturer=Molex, Supplier Part Number 1=WM7877-ND
J2: library part CMP-0055340-2, "Terminal Block, 3.5 mm, 3x1, Tin, TH", Manufacturer=Molex, Supplier Part Number 1=WM7878-ND
L1: library part CMP-0098714-1, "WE-HCC SMT High Current Cube Inductor, size 1090, 10uH, 9A, 23.1mOhm", Case/Size Code=1090, DC Resistance=22.75mOhm, DC Resistance Max=23.1mOhm, Inductance=10uH, Manufacturer="Wurth Elektronik", Manufacturer Part Number=7443331000, Operating Temperature Max=125°C, Operating Temperature Min=-40°C, Rated Current=9A, Rated Inductance=5.5uH, Saturation Current=11.7A, Self Resonant Frequency=35MHz
L2: library part CMP-0064762-2, "Inductor, Shielded Drum Core, Ferrite, 820 uH, 0.95 A, 1 ohm, SMD", Manufacturer="Wurth Elektronik", Supplier Part Number 1=732-1701-1-ND, Value1="1 ohm", Value2=0.95A, ValueDisplayed=820uH
L4: library part CMP-0086690-2, "Power Common Mode Choke", Manufacturer="Wurth Electronics"
L5: library part CMP-0013122-1, "Coupled inductor, 20 mH, 1.5 A, 0.27 ohm, TH", Manufacturer="Wurth Elektronik", Supplier Part Number 1=732-1448-ND, ValueDisplayed=20mH
Q1: library part CMP-0086795-1, "N-Channel 650V 9A (Tc) 22W (Tc) Through Hole PG-TO220 Full Pack", Manufacturer=Infineon, PartNumber=IPAW60R360P7SXKSA1
Q2: library part CMP-0086019-2, "OPTOISOLATOR 3.75KV TRANS 4-SO", Manufacturer=Toshiba
R1: "RES, 10.0, 0.1%, 0.063 W, 0402", Manufacturer="TE Connectivity", PartNumber=CPF0402B10RE1, Power_W=63mW, Supplier Part Number 1=A102583CT-ND, TempCo="25 ppm/C", Tolerance_%=0.1%, Value2=0.063W, Value_Code=10R0, ValueDisplayed=10.0
R2 R3: library part CMP-0092204-1, "100 kOhms ±1% 0.063W, 1/16W Chip Resistor 0402 (1005 Metric)  Thick Film", Digikey Part Number=541-3960-1-ND, Manufacturer=Vishay, Mouser Part Number=71-CRCW0402100KFKEDC, Operating Temperature Range="-55°C to +155°C", Power_W=63mW, TempCo=100ppm/°C, Tolerance_%=1%
R4: library part CMP-0027506-1, "RES, 23.7 k, 1%, 0.05 W, 0201", Manufacturer="Yageo America", Power_W=50mW, Supplier Part Number 1=YAG2524CT-ND, TempCo="200 ppm/C", Tolerance_%=1%, Value2=0.05W, Value_Code=23k7, ValueDisplayed=23.7k
R5 R20 R21: "RES, 750 k, 1%, 0.25 W, AEC-Q200 Grade 0, 1206", Manufacturer=Vishay-Dale, PartNumber=CRCW1206750KFKEA, Power_W=250mW, Supplier Part Number 1=541-750KFCT-ND, TempCo="100 ppm/C", Tolerance_%=1%, Value2=0.25W, Value_Code=750k
R6: "RES, 10, 5%, 0.125 W, 0805", Manufacturer="Yageo America", PartNumber=RC0805JR-0710RL, Power_W=125mW, Supplier Part Number 1=311-10ARCT-ND, TempCo="200 ppm/C", Tolerance_%=5%, Value2=0.125W, Value_Code=10R0, ValueDisplayed=10
R7: "RES, 86.6 k, 1%, 0.1 W, AEC-Q200 Grade 0, 0603", Manufacturer=Vishay-Dale, PartNumber=CRCW060386K6FKEA, Power_W=100mW, Supplier Part Number 1=541-86.6KHCT-ND, TempCo="100 ppm/C", Tolerance_%=1%, Value2=0.1W, Value_Code=86k6, ValueDisplayed=86.6k
R8: "RES, 1.50 k, 1%, 0.1 W, 0603", Manufacturer=Yageo, PartNumber=RC0603FR-071K5L, Power_W=100mW, Supplier Part Number 1=311-1.50KHRCT-ND, TempCo="100 ppm/C", Tolerance_%=1%, Value2=0.1W, Value_Code=1k50, ValueDisplayed=1.50k
R9: "RES, 383 k, 0.1%, 0.1 W, 0603", Manufacturer="Yageo America", PartNumber=RT0603BRD07383KL, Power_W=100mW, TempCo="25 ppm/C", Tolerance_%=0.1%, Value2=0.1W, Value_Code=383k
R10: "RES, 10, 5%, 0.1 W, AEC-Q200 Grade 0, 0603", Manufacturer=Vishay-Dale, PartNumber=CRCW060310R0JNEA, Power_W=100mW, Supplier Part Number 1=541-10GCT-ND, TempCo="200 ppm/C", Tolerance_%=5%, Value2=0.1W, Value_Code=10R0, ValueDisplayed=10
R11: "RES, 22.1 k, 1%, 0.1 W, AEC-Q200 Grade 0, 0603", Manufacturer=Vishay-Dale, PartNumber=CRCW060322K1FKEA, Power_W=100mW, Supplier Part Number 1=541-22.1KHCT-ND, TempCo="100 ppm/C", Tolerance_%=1%, Value2=0.1W, Value_Code=22k1, ValueDisplayed=22.1k
R12: "RES, 330 k, 5%, 0.25 W, AEC-Q200 Grade 0, 1206", Manufacturer=Vishay-Dale, PartNumber=CRCW1206330KJNEA, Power_W=250mW, Supplier Part Number 1=541-330KECT-ND, TempCo="200 ppm/C", Tolerance_%=5%, Value2=0.25W, Value_Code=330k
R13: library part CMP-0022711-2, "RES, 2.20, 1%, 0.1 W, 0603", Manufacturer=Panasonic, Power_W=100mW, Supplier Part Number 1=P2.2AJCT-ND, TempCo="200 ppm/C", Tolerance_%=1%, Value2=0.1W, Value_Code=2R20, ValueDisplayed=2.20
R14: "RES, 1.00 k, 1%, 0.1 W, AEC-Q200 Grade 0, 0603", Manufacturer=Vishay-Dale, PartNumber=CRCW06031K00FKEA, Power_W=100mW, Supplier Part Number 1=541-1.00KHCT-ND, TempCo="100 ppm/C", Tolerance_%=1%, Value2=0.1W, Value_Code=1k00, ValueDisplayed=1.00k
R15: "RES, 100 k, 1%, 0.1 W, 0603", Manufacturer=Yageo, PartNumber=RC0603FR-07100KL, Power_W=100mW, Supplier Part Number 1=311-100KHRCT-ND, TempCo="100 ppm/C", Tolerance_%=1%, Value2=0.1W, Value_Code=100k
R16: "RES, 22.0 k, 1%, 0.1 W, 0603", Manufacturer=Yageo, PartNumber=RC0603FR-0722KL, Power_W=100mW, Supplier Part Number 1=311-22.0KHRCT-ND, TempCo="100 ppm/C", Tolerance_%=1%, Value2=0.1W, Value_Code=22k0, ValueDisplayed=22.0k
R17: "RES, 0.33, 1%, 0.25 W, AEC-Q200 Grade 0, 1206", Manufacturer=Panasonic, PartNumber=ERJ-8RQFR33V, Power_W=250mW, Supplier Part Number 1=P.33RCT-ND, TempCo="250 ppm/C", Tolerance_%=1%, Value2=0.25W, Value_Code=R330, ValueDisplayed=0.33
R18: "RES, 4.99 k, 0.1%, 0.063 W, 0603", Manufacturer="TE Connectivity", PartNumber=CPF0603B4K99E, Power_W=63mW, Supplier Part Number 1=8-1879219-3-ND, TempCo="25 ppm/C", Tolerance_%=0.1%, Value2=0.063W, Value_Code=4k99, ValueDisplayed=4.99k
R19: "RES, 44.2 k, 1%, 0.1 W, 0603", Manufacturer=Yageo, PartNumber=RC0603FR-0744K2L, Power_W=100mW, Supplier Part Number 1=311-44.2KHRCT-ND, TempCo="100 ppm/C", Tolerance_%=1%, Value2=0.1W, Value_Code=44k2, ValueDisplayed=44.2k
R22: "RES, 10.0 k, 1%, 0.1 W, AEC-Q200 Grade 0, 0603", Manufacturer=Vishay-Dale, PartNumber=CRCW060310K0FKEA, Power_W=100mW, Supplier Part Number 1=541-10.0KHCT-ND, TempCo="100 ppm/C", Tolerance_%=1%, Value2=0.1W, Value_Code=10k0, ValueDisplayed=10.0k
R23 R26: "RES, 47 k, 5%, 2 W, AEC-Q200 Grade 0, Axial resistor", Manufacturer=Vishay-Bccomponents, PartNumber=PR02000204702JR500, Power_W=2W, Supplier Part Number 1=PPC47KW-2CT-ND, TempCo="250 ppm/C", Tolerance_%=5%, Value_Code=47k0, ValueDisplayed=47k
R24: "RES, 2.4 k, 5%, 0.063 W, AEC-Q200 Grade 0, 0402", Manufacturer=Vishay-Dale, PartNumber=CRCW04022K40JNED, Power_W=63mW, Supplier Part Number 1=541-2.4KJCT-ND, TempCo="200 ppm/C", Tolerance_%=5%, Value2=0.063W, Value_Code=2k40, ValueDisplayed=2.4k
R25: "RES, 0, 5%, 0.1 W, AEC-Q200 Grade 0, 0603", Manufacturer=Vishay-Dale, PartNumber=CRCW06030000Z0EA, Power_W=100mW, Supplier Part Number 1=541-0.0GCT-ND, TempCo="200 ppm/C", Tolerance_%=5%, Value2=0.1W, Value_Code=0000, ValueDisplayed=0
R27: "RES, 120 k, 1%, 0.063 W, AEC-Q200 Grade 0, 0402", Manufacturer=Vishay-Dale, PartNumber=CRCW0402120KFKED, Power_W=63mW, Supplier Part Number 1=541-120KLCT-ND, TempCo="100 ppm/C", Tolerance_%=1%, Value2=0.063W, Value_Code=120k
R28: "RES, 100 k, 1%, 0.1 W, AEC-Q200 Grade 0, 0603", Manufacturer=Vishay-Dale, PartNumber=CRCW0603100KFKEA, Power_W=100mW, Supplier Part Number 1=541-100KHCT-ND, TempCo="100 ppm/C", Tolerance_%=1%, Value2=0.1W, Value_Code=100k
R29: "RES, 10.0 k, 1%, 0.1 W, 0603", Manufacturer=Yageo, PartNumber=RC0603FR-0710KL, Power_W=100mW, Supplier Part Number 1=311-10.0KHRCT-ND, TempCo="100 ppm/C", Tolerance_%=1%, Value2=0.1W, Value_Code=10k0, ValueDisplayed=10.0k
R30: "RES, 47, 5%, 0.25 W, AEC-Q200 Grade 0, 1206", Manufacturer=Vishay-Dale, PartNumber=CRCW120647R0JNEA, Power_W=250mW, Supplier Part Number 1=541-47ECT-ND, TempCo="200 ppm/C", Tolerance_%=5%, Value2=0.25W, Value_Code=47R0, ValueDisplayed=47
R31: "RES, 10.0, 1%, 0.125 W, AEC-Q200 Grade 0, 0805", Manufacturer=Vishay-Dale, PartNumber=CRCW080510R0FKEA, Power_W=125mW, Supplier Part Number 1=541-10.0CCT-ND, TempCo="100 ppm/C", Tolerance_%=1%, Value2=0.125W, Value_Code=10R0, ValueDisplayed=10.0
RT1: library part CMP-0002554-2, "Thermistor NTC, 4.70 ohm, 20%, 15x7mm", Manufacturer=TDK, Power_W=3.1W, Supplier Part Number 1=495-2099-ND, Tolerance_%=20%
T1: library part ER28-17, "300uH, ER28-17,TH", Manufacturer=Wurth
TP1: library part CMP-0055148-1, "Test Point, Multipurpose, Black, TH", Color=Black, Manufacturer=Keystone, Supplier Part Number 1=36-5011-ND
U1: library part CMP-0074756-2, "3.8V to 36V 3A/2A Synchronous Step-Down Voltage Regulator, DDA0008J (SOIC-8)", Alternate Manufacturer="Texas Instruments", Alternate PartNumber=LMR33620ADDA
U2: library part CMP-0067235-2, "Constant-Voltage, Constant-Current Flyback Controller Using Opto-Coupler Feedback, D0007A (SOIC-7)", Alternate Manufacturer="Texas Instruments", Alternate PartNumber=UCC28740D
U3: "Optocoupler, 5 kV, 50-600% CTR, SMT", Manufacturer=Lite-On, Supplier Part Number 1=160-1367-5-ND, Voltage_Isolation_Vrms=5000V
U4: library part CMP-0084725-1, "Programmable Shunt Regulator with Optimized Reference Current, DBZ0003A (SOT-23-3)", Alternate Manufacturer="Texas Instruments"

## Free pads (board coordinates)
  round 1.6 hole 1.1: 1(34.214,37.008) 1(34.279,72.974)

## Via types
v1: diameter 0.4, hole 0.2, Top Layer to Bottom Layer, 2240 vias
v2: diameter 0.66, hole 0.33, Top Layer to Bottom Layer, 1066 vias
v3: diameter 0.5, hole 0.2, Top Layer to Bottom Layer, 105 vias
v4: diameter 0.67, hole 0.33, Top Layer to Bottom Layer, tented both sides, 41 vias
v5: diameter 0.5, hole 0.2, Top Layer to Bottom Layer, tented both sides, 4 vias
v6: diameter 0.61, hole 0.203, Top Layer to Bottom Layer, tented both sides, 2 vias

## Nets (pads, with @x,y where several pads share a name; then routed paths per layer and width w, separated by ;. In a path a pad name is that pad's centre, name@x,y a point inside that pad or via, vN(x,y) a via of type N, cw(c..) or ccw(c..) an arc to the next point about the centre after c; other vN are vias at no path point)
5V: C6.1 C7.1 C8.1 C9.1 C19.1 J1.1 L1.2 Q2.4 R1.2 | length 95.9
  Top Layer w0.3: Q2.4@116.603,11.053 117.148,11.053 118.516,12.421 v3(123.698,12.421) ; R1.2@141.953,32.512 v3(142.672,32.512)
  Bottom Layer w0.3: v3(123.698,12.421) 125.146,12.421 134.671,2.896 165.783,2.896 J1.1@168.3,5.413 ; v3(142.672,32.512) 143.231,33.071 148.488,33.071 154.991,26.568 154.991,10.033 v3(159.334,5.69)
